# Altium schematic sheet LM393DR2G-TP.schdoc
size 127 x 101 mm
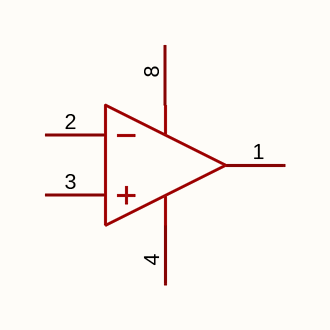
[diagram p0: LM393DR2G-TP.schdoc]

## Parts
U?  lm393dr2g-tp  [SOP-8_L4.9-W3.9-P1.27-LS6.0-BL]  (value not drawn)  (part A of 2)

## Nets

Not connected (* = marked no-connect by the designer): U? 1(OUT1) 2(IN1-) 3(IN1+) 4(-VS) 8(+VS)

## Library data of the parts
U? = lm393dr2g-tp: 比较器数:双路;输入失调电压(Vos):4mV;输入偏置电流(Ib):65nA;; Manufacturer: TECH PUBLIC(台舟); AddInBom: yes; ModelId: 75c24a7891ee4dd6bdac16a7163ff87e; ModelName: SOP-8_L4.9-W3.9-P1.27-LS6.0-BL-1; ModelTransform: 192.913,236.22,0,0,0,0,-0.393,2.749,0; Number of Channels: 双路; Vos - Input Offset Voltage: 4mV; Ib - Input Bias Current: 65nA; Output Mode: CMOS；TTL; Quiescent Current: 600uA; Maximum Power Supply Range (Vdd-Vss): 30V; Single Supply: 3V~30V; Dual Supply: -15V~-1.5V；1.5V~15V; Input Offset Current(Ios): 5nA; Response Time (tr): 1.4us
